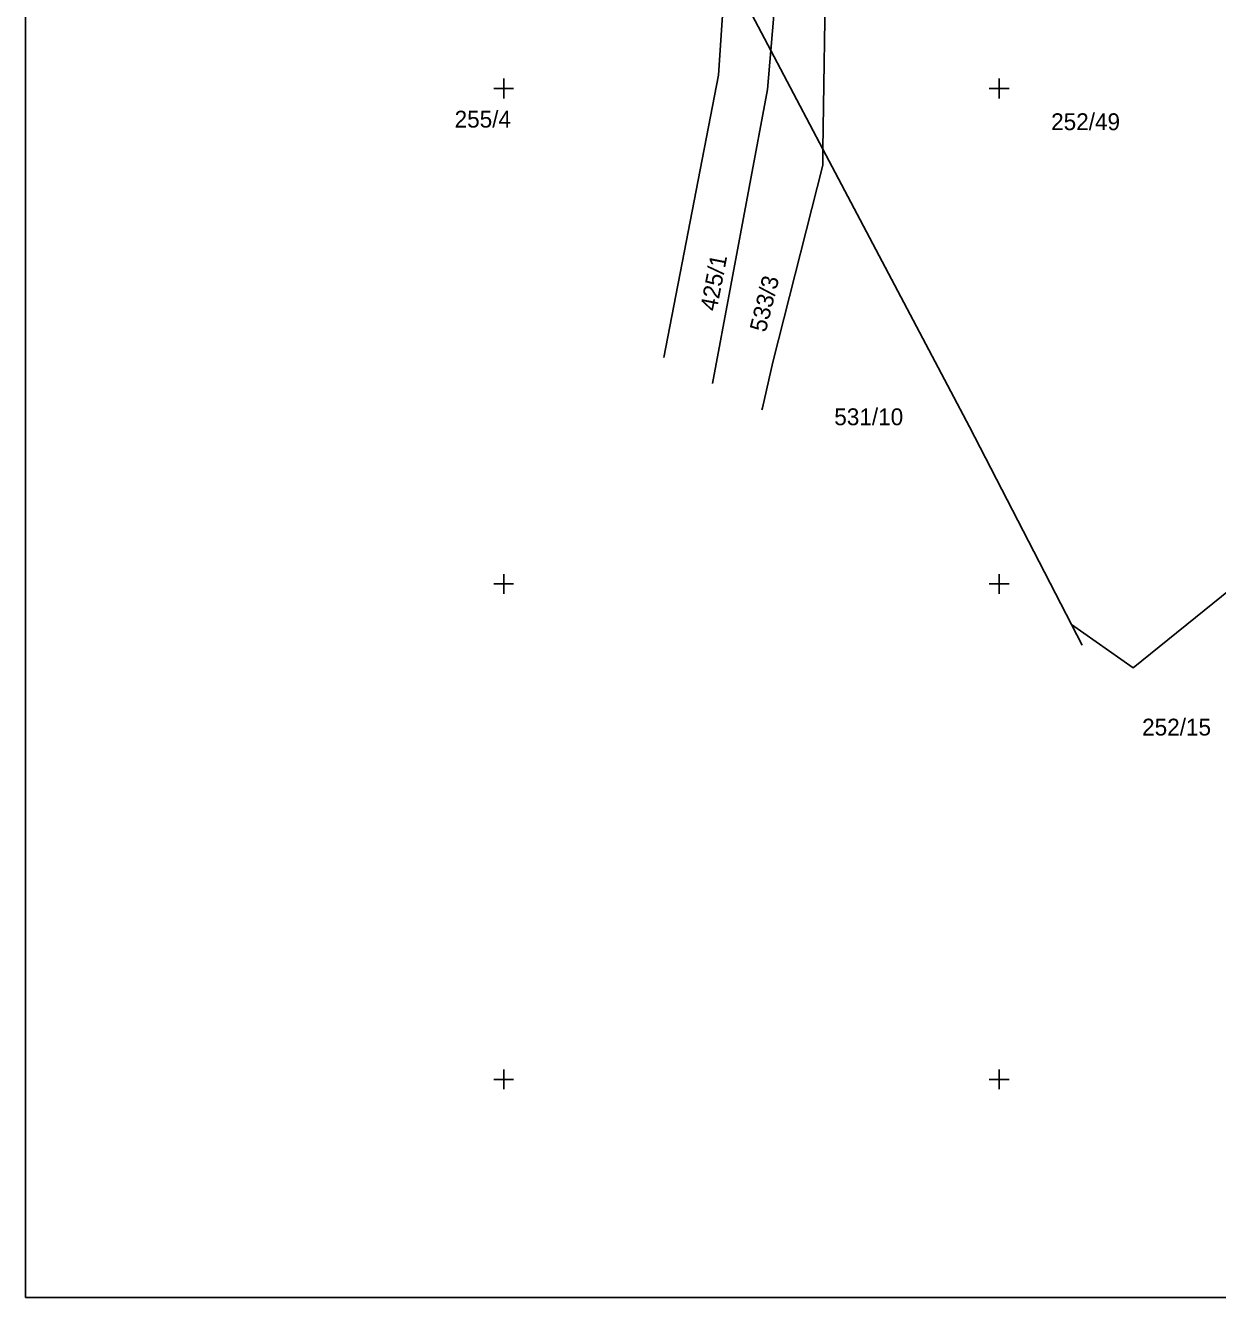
# Model space of a CAD drawing. Extents: x -645398 to -644998, y -1063322 to -1063031.
# Drawn here: x -645398.3 to -645278, y -1063322 to -1063193.6 of the extents above; entities that cross this region are included whole.
import ezdxf

# ---------------------------------------------------------------- set-up
doc = ezdxf.new("R2010")
doc.units = 0
for name, color, linetype in [('Hranice KN pozemků', 7, 'Continuous'), ('Rámeček', 7, 'Continuous'), ('Souřadnicové křížky', 7, 'Continuous'), ('Čísla parcel', 7, 'Continuous')]:
    doc.layers.add(name, color=color, linetype=linetype)

msp = doc.modelspace()

# ---------------------------------------------------------------- linework, layer by layer
at = {"layer": 'Hranice KN pozemků'}
for p, q in [((-645323.05, -1063196.15), (-645327.59, -1063187.55)), ((-645323.05, -1063196.15), (-645317.79, -1063206.12)), ((-645291.63, -1063256.17), (-645292.7, -1063254.09))]:
    msp.add_line(p, q, dxfattribs=at)
for points in [[(-645323.05, -1063196.15), (-645321.82, -1063181.84), (-645322.75, -1063165.35), (-645321.76, -1063149.91)], [(-645318.7, -1063152.02), (-645318.41, -1063159.59), (-645317.49, -1063186.56), (-645317.79, -1063206.12)], [(-645327.59, -1063187.55), (-645328.31, -1063198.66), (-645333.85, -1063227.16)], [(-645328.93, -1063229.78), (-645323.39, -1063200.11), (-645323.05, -1063196.15)], [(-645317.79, -1063206.12), (-645317.81, -1063207.72), (-645322.83, -1063227.61), (-645323.89, -1063232.21), (-645323.94, -1063232.44)], [(-645317.79, -1063206.12), (-645302.99, -1063234.15), (-645292.7, -1063254.09)], [(-645292.7, -1063254.09), (-645286.48, -1063258.46), (-645276.71, -1063250.55)]]:
    msp.add_lwpolyline(points, dxfattribs=at)
at = {"layer": 'Rámeček'}
for p, q in [((-645398.25, -1063031.02), (-645398.25, -1063322.02)), ((-645398.25, -1063322.02), (-644998.25, -1063322.02))]:
    msp.add_line(p, q, dxfattribs=at)
at = {"layer": 'Souřadnicové křížky'}
for p, q in [((-645350, -1063199), (-645350, -1063201)), ((-645300, -1063199), (-645300, -1063201)), ((-645349, -1063200), (-645351, -1063200)), ((-645299, -1063200), (-645301, -1063200)), ((-645350, -1063249), (-645350, -1063251)), ((-645300, -1063249), (-645300, -1063251)), ((-645349, -1063250), (-645351, -1063250)), ((-645299, -1063250), (-645301, -1063250)), ((-645350, -1063299), (-645350, -1063301)), ((-645300, -1063299), (-645300, -1063301)), ((-645349, -1063300), (-645351, -1063300)), ((-645299, -1063300), (-645301, -1063300))]:
    msp.add_line(p, q, dxfattribs=at)

# ---------------------------------------------------------------- texts
at = {"layer": 'Čísla parcel'}
for s, p in [('255/4', (-645354.95, -1063203.94)), ('252/49', (-645294.76, -1063204.2)), ('531/10', (-645316.64, -1063233.98)), ('252/15', (-645285.58, -1063265.3))]:
    msp.add_text(s, height=1.7, dxfattribs=at).set_placement(p)
for s, rotation, p in [('425/1', 79, (-645328.52, -1063222.54)), ('533/3', 76, (-645323.56, -1063224.67))]:
    msp.add_text(s, height=1.7, rotation=rotation, dxfattribs=at).set_placement(p)

doc.saveas('drawing.dxf')
